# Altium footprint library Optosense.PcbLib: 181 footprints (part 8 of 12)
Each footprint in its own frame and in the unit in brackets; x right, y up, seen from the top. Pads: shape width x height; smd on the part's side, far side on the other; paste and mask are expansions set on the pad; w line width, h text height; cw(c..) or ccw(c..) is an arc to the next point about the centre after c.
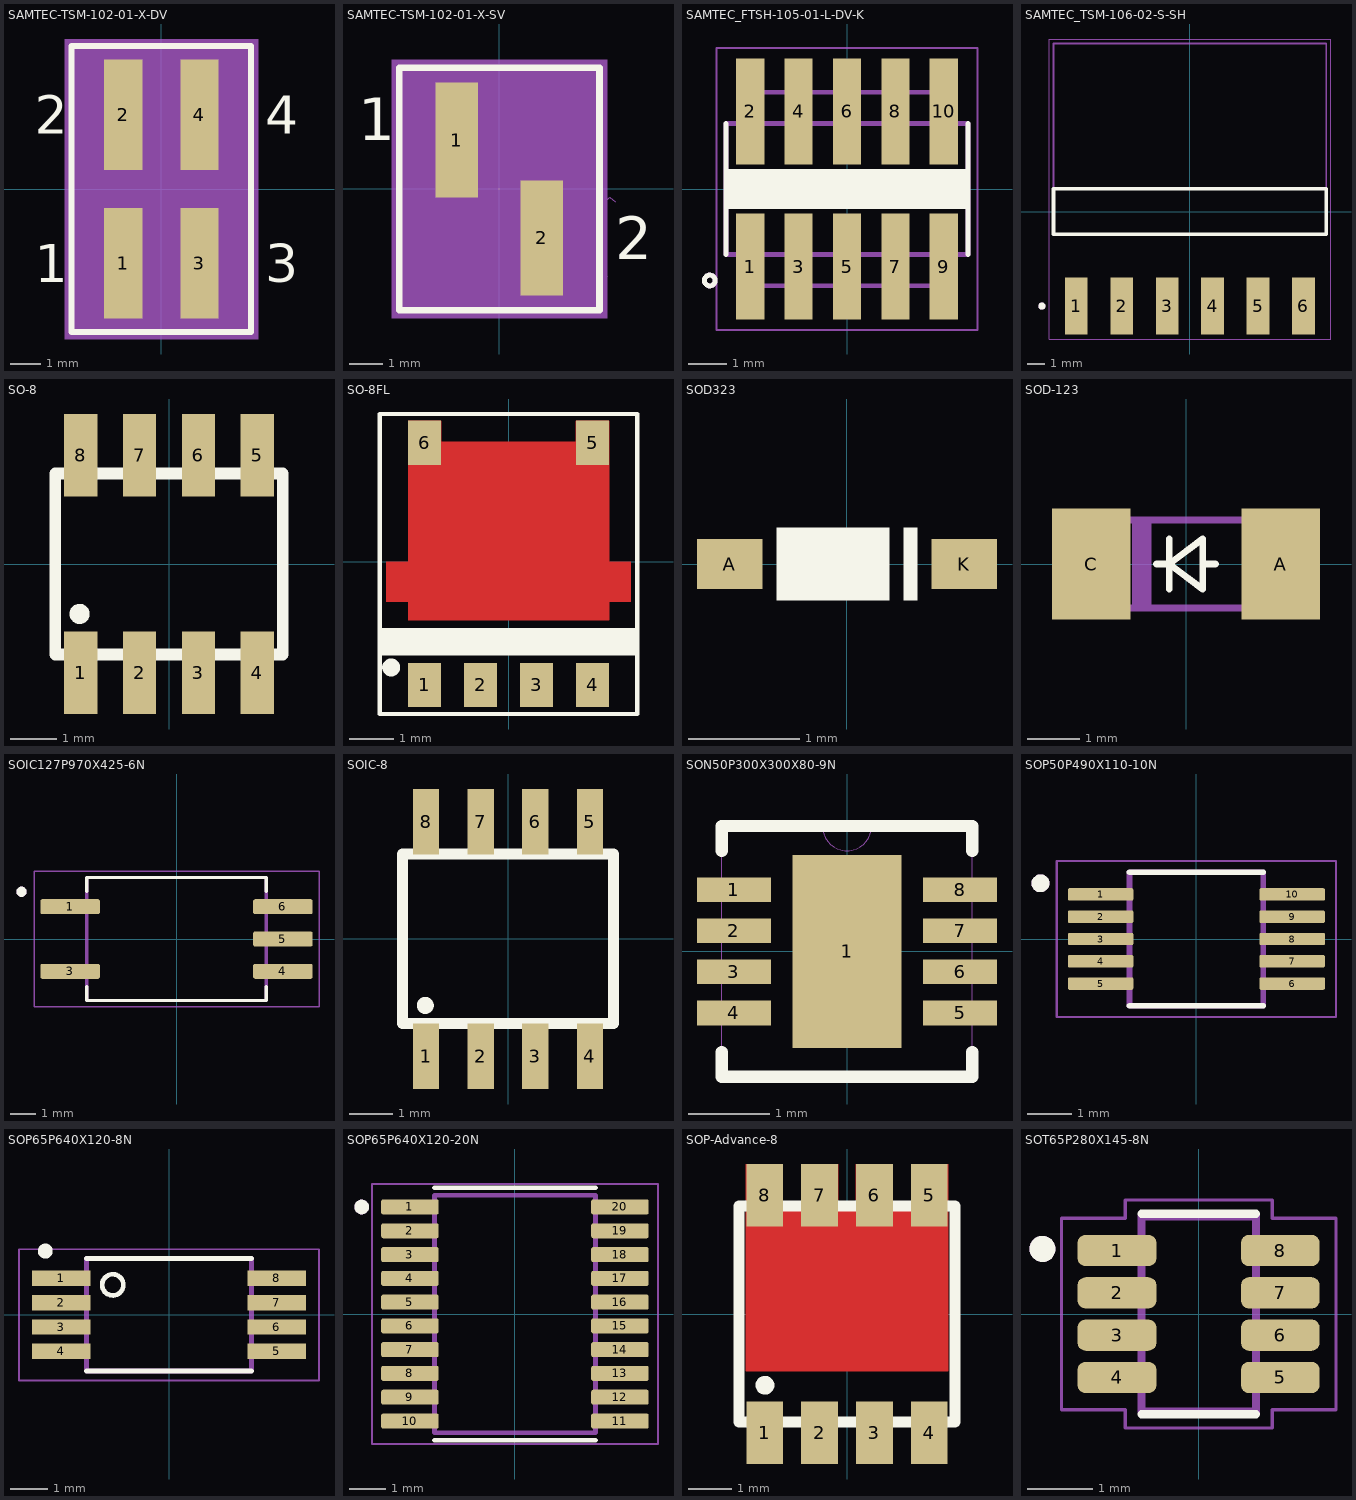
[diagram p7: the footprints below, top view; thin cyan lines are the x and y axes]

## SAMTEC-TSM-102-01-X-DV [mm]
pads (4):
  rect 1.27x3.68 smd mask+0: 1(-1.27,-2.476) 2(-1.27,2.476) 3(1.27,-2.476) 4(1.27,2.476)
Top Overlay:
  lines w0.2: -2.99,-4.768 2.99,-4.768 2.99,4.768 -2.99,4.768 -2.99,-4.768
  text "3" at 3.467,-3.112 h1.27
  text "2" at -4.226,1.842 h1.27
  text "1" at -4.226,-3.112 h1.27
  text "4" at 3.467,1.842 h1.27
Top Paste:
  region: 1.905,0.636 0.635,0.636 0.635,4.316 1.905,4.316
  region: 1.905,-4.316 0.635,-4.316 0.635,-0.636 1.905,-0.636
  region: -0.635,0.636 -1.905,0.636 -1.905,4.316 -0.635,4.316
  region: -0.635,-4.316 -1.905,-4.316 -1.905,-0.636 -0.635,-0.636
Top Solder:
  region: 1.956,0.585 0.584,0.585 0.584,4.367 1.956,4.367
  region: 1.956,-4.367 0.584,-4.367 0.584,-0.585 1.956,-0.585
  region: -0.584,0.585 -1.956,0.585 -1.956,4.367 -0.584,4.367
  region: -0.584,-4.367 -1.956,-4.367 -1.956,-0.585 -0.584,-0.585
Mechanical 13:
  lines w0: -0.635,4.699 0.635,4.699
  lines w0.1: -2.35,-0.762 -2.54,-0.762 -2.54,0.762 -2.35,0.762 ; -1.588,-2.54 -1.588,-3.848 -0.952,-3.848 -0.952,-2.54 ; -1.588,2.54 -1.588,3.848 -0.952,3.848 -0.952,2.54 ; -0.19,-0.762 0,-0.762 ; -0.19,0.762 0,0.762 ; 0.19,-0.762 0,-0.762 ; 0.19,0.762 0,0.762 ; 0.952,-2.54 0.952,-3.848 1.588,-3.848 1.588,-2.54 ; 0.952,2.54 0.952,3.848 1.588,3.848 1.588,2.54 ; 2.35,-0.762 2.54,-0.762 2.54,0.762 2.35,0.762 ; 0,-0.762 0,0.762 ; 0,-0.762 0,0.762 ; -2.99,-4.768 2.99,-4.768 2.99,4.768 -2.99,4.768 -2.99,-4.768 ; -2.35,-1.651 -2.35,-0.147 -1.905,-0.147 -1.905,0.147 -2.35,0.147 -2.35,1.651 -1.968,2.54 -0.572,2.54 -0.19,1.651 -0.19,0.147 -0.635,0.147 -0.635,-0.147 -0.19,-0.147 -0.19,-1.651 -0.572,-2.54 -1.968,-2.54 -2.35,-1.651 ; -1.588,-1.588 -0.952,-1.588 -0.952,-0.952 -1.588,-0.952 -1.588,-1.588 ; -1.588,0.952 -1.588,1.588 -0.952,1.588 -0.952,0.952 -1.588,0.952 ; 0.19,-1.651 0.19,-0.147 0.635,-0.147 0.635,0.147 0.19,0.147 0.19,1.651 0.572,2.54 1.968,2.54 2.35,1.651 2.35,0.147 1.905,0.147 1.905,-0.147 2.35,-0.147 2.35,-1.651 1.968,-2.54 0.572,-2.54 0.19,-1.651 ; 0.952,-1.588 1.588,-1.588 1.588,-0.952 0.952,-0.952 0.952,-1.588 ; 0.952,0.952 0.952,1.588 1.588,1.588 1.588,0.952 0.952,0.952
  text "3" at 3.467,-3.112 h1.27
  text "2" at -4.226,1.842 h1.27
  text "1" at -4.226,-3.112 h1.27
  text "4" at 3.467,1.842 h1.27
Mechanical 15:
  region: 3.225,-5.003 -3.225,-5.003 -3.225,5.003 3.225,5.003
3D body "TSM-102-01-F-DV.stp": height 9.61, standoff -0.04, extent -2.54,-3.848 2.54,3.848

## SAMTEC-TSM-102-01-X-SV [mm]
pads (2):
  rect 1.27x3.43 smd mask+0: 1(-1.27,1.46) 2(1.27,-1.46)
Top Overlay:
  lines w0.2: -2.99,-3.627 2.99,-3.627 2.99,3.626 -2.99,3.626 -2.99,-3.627
  text "2" at 3.467,-2.096 h1.27
  text "1" at -4.226,1.46 h1.27
Top Paste:
  region: 1.905,-3.175 0.635,-3.175 0.635,0.255 1.905,0.255
  region: -0.635,-0.255 -1.905,-0.255 -1.905,3.175 -0.635,3.175
Top Solder:
  region: 1.956,-3.226 0.584,-3.226 0.584,0.306 1.956,0.306
  region: -0.584,-0.306 -1.956,-0.306 -1.956,3.226 -0.584,3.226
Mechanical 13:
  lines w0: 3.143,-2.54 3.223,-2.604 ; 3.143,-0.381 3.302,-0.254 ; 3.223,-0.318 3.302,-0.254 ; 3.381,-0.318 3.461,-0.381 3.302,-0.254
  lines w0.1: -1.586,0.318 -0.951,0.318 ; -1.586,0.318 -1.586,1.27 -1.586,2.642 -0.951,2.642 -0.951,1.27 -0.951,0.318 ; -1.586,0.318 -1.586,-0.318 -0.951,-0.318 -0.951,0.318 ; 0,-1.016 0.106,-1.016 0.253,-1.27 2.54,-1.27 2.54,-1.016 2.54,1.016 2.54,1.27 0.253,1.27 0.106,1.016 0,1.016 ; 0,-1.016 0,1.016 ; 0,-1.016 -0.106,-1.016 -0.253,-1.27 -2.54,-1.27 -2.54,-1.016 -2.54,1.016 -2.54,1.27 -0.253,1.27 -0.106,1.016 0,1.016 ; 0,-1.016 0,1.016 ; 0.951,-0.318 1.586,-0.318 ; 0.951,-0.318 0.951,0.318 1.586,0.318 1.586,-0.318 ; 0.951,-0.318 0.951,-1.27 0.951,-2.642 1.586,-2.642 1.586,-1.27 1.586,-0.318 ; -2.99,-3.627 2.99,-3.627 2.99,3.626 -2.99,3.626 -2.99,-3.627
  text "2" at 3.467,-2.096 h1.27
  text "1" at -4.226,1.46 h1.27
Mechanical 15:
  region: 3.225,-3.862 -3.225,-3.862 -3.225,3.861 3.225,3.861
3D body "TSM-102-01-F-SV.stp": height 9.65, standoff 0, extent -2.54,-2.641 2.54,2.642

## SAMTEC_FTSH-105-01-L-DV-K [mm]
pads (10):
  rect 0.74x2.79 smd: 1(-2.54,-2.035) 2(-2.54,2.035) 3(-1.27,-2.035) 4(-1.27,2.035) 5(0,-2.035) 6(0,2.035) 7(1.27,-2.035) 8(1.27,2.035) 9(2.54,-2.035) 10(2.54,2.035)
Top Overlay:
  circle w0.127: c-3.6,-2.4 r0.141
  rectangle: -3.175,-0.525 3.175,0.525
  lines w0.127: -3.175,-1.715 -3.175,1.715 ; 3.175,-1.715 3.175,1.715
Mechanical 13:
  circle w0.127: c-3.6,-2.4 r0.141
  lines w0.127: -2.54,-1.715 -3.175,-1.715 -3.175,1.715 -2.54,1.715 ; -2.54,-1.715 2.54,-1.715 ; -2.54,-1.715 -2.54,-2.54 2.54,-2.54 2.54,-1.715 ; -2.54,1.715 2.54,1.715 ; -2.54,1.715 -2.54,2.54 2.54,2.54 2.54,1.715 ; 2.54,-1.715 3.175,-1.715 3.175,1.715 2.54,1.715
Mechanical 15:
  lines w0.05: -3.425,-3.7 3.425,-3.7 3.425,3.7 -3.425,3.7 -3.425,-3.7
3D body "FTSH-105-01-L-DV-K.stp": height 6.11, standoff -0.01, extent -3.175,-2.921 3.175,2.921

## SAMTEC_TSM-106-02-S-SH [mm]
pads (6):
  rect 1.27x3.18 smd: 1(-6.35,-5.28) 2(-3.81,-5.28) 3(-1.27,-5.28) 4(1.27,-5.28) 5(3.81,-5.28) 6(6.35,-5.28)
Top Overlay:
  circle w0.2: c-8.27,-5.28 r0.1
  lines w0.2: -7.62,-1.27 7.62,-1.27 7.62,1.27 -7.62,1.27 -7.62,-1.27
Mechanical 13:
  circle w0.2: c-8.27,-5.28 r0.1
  lines w0.1: -7.62,-1.27 -7.62,9.4 7.62,9.4 7.62,-1.27 ; -7.62,-1.27 7.62,-1.27 ; -7.62,-1.27 -7.62,1.27 7.62,1.27 7.62,-1.27
Mechanical 15:
  lines w0.05: -7.87,-7.12 7.87,-7.12 7.87,9.65 -7.87,9.65 -7.87,-7.12
3D body "TSM-106-02-S-SH-P.stp": height 4.32, standoff 0, extent -7.62,-6.096 7.62,9.398

## SO-8 [mm]
height 1.55
pads (8):
  rect 0.72x1.78 smd: 1(-1.905,-2.34) 2(-0.635,-2.34) 3(0.635,-2.34) 4(1.905,-2.34) 5(1.905,2.34) 6(0.635,2.34) 7(-0.635,2.34) 8(-1.905,2.34)
Top Overlay:
  circle w0.254: c-1.925,-1.075 r0.09
  lines w0.254: -2.45,-1.95 2.45,-1.95 2.45,1.95 -2.45,1.95 -2.45,-1.95
3D body "CircuitWorks-SO-8.step": height 1.45, standoff 0, extent -2.438,-2.889 2.464,2.889

## SO-8FL [mm]
pads (6):
  rect 0.75x1 smd: 1(-1.905,-2.795) 2(-0.635,-2.795) 3(0.635,-2.795) 4(1.905,-2.795) 5(1.905,2.7) 6(-1.905,2.7)
Top Layer:
  rectangle: -0.94,-0.178 0.94,1.676
  region: -2.28,-1.33 2.28,-1.33 2.28,-0.905 2.775,-0.905 2.775,0 2.28,0 2.28,3.2 1.53,3.2 1.53,2.725 -1.53,2.725 -1.53,3.2 -2.28,3.2 -2.28,0 -2.775,0 -2.775,-0.905 -2.28,-0.905
Top Overlay:
  circle w0.2: c-2.665,-2.398 r0.103
  rectangle: -2.946,-2.125 2.921,-1.499
  lines w0.1: -2.921,-3.454 2.921,-3.454 2.921,3.353 -2.921,3.353 -2.921,-3.454
3D body "User Library-DFN8-5X6 DUAL.step": height 1.1, standoff 0, extent -2.575,-3.1 2.575,3.05

## SOD323 [mm]
pads (2):
  rect 0.59x0.45 smd: A(-1.055,0) K(1.055,0)
Top Overlay:
  rectangle: -0.635,-0.33 0.381,0.33
  rectangle: 0.508,-0.33 0.635,0.33
3D body "User Library-SOD-323.STEP": height -0.4, standoff -1.5, extent -1.305,-0.69 1.295,0.66

## SOD-123 [mm]
pads (2):
  rect 1.5x2.1 smd: A(1.8,0) C(-1.8,0)
Top Overlay:
  lines w0.127: -0.561,0 -0.318,0 ; -0.318,-0.476 -0.318,0 ; -0.318,0.476 -0.318,0 ; 0.561,0 0.318,0 ; -0.318,0 0.318,-0.476 0.318,0 ; -0.318,0 0.318,0.476 0.318,0
Mechanical 13:
  region: -1.587,-0.9 -1.95,-0.9 -1.95,0.9 -1.587,0.9
  region: 1.95,-0.9 1.587,-0.9 1.587,0.9 1.95,0.9
  region: -0.663,-0.9 -1.025,-0.9 -1.025,0.9 -0.663,0.9
  lines w0.127: -1.873,-0.835 1.873,-0.835 ; -1.873,0.835 1.873,0.835
3D body "MMSZ4684.STEP": height 1.44, standoff -0.01, extent -1.825,-0.775 1.825,0.775

## SOIC127P970X425-6N [mm]
pads (5):
  rrect25% 2.34x0.59 smd: 1(-4.185,1.27) 3(-4.185,-1.27) 4(4.185,-1.27) 5(4.185,0) 6(4.185,1.27)
Top Overlay:
  circle w0.2: c-6.1,1.86 r0.1
  lines w0.127: -3.53,-1.88 -3.53,-2.42 3.53,-2.42 3.53,-1.88 ; -3.53,1.88 -3.53,2.42 3.53,2.42 3.53,1.88
Mechanical 13:
  circle w0.2: c-6.1,1.86 r0.1
  lines w0.127: -3.53,-2.42 -3.53,2.42 3.53,2.42 3.53,-2.42 -3.53,-2.42
Mechanical 15:
  lines w0.05: -5.605,-2.67 -5.605,2.67 5.605,2.67 5.605,-2.67 -5.605,-2.67
3D body "User Library-4 Lead 6 SOIC.STEP": height 2.3, standoff 0, extent -3.171,-1.85 3.172,1.85

## SOIC-8 [mm]
pads (8):
  rect 0.61x1.52 smd: 1(-1.905,-2.735) 2(-0.635,-2.735) 3(0.635,-2.735) 4(1.905,-2.735) 5(1.905,2.725) 6(0.635,2.725) 7(-0.635,2.725) 8(-1.905,2.725)
Top Overlay:
  circle w0.254: c-1.925,-1.55 r0.071
  lines w0.254: -2.45,-1.975 -2.45,1.975 2.45,1.975 2.45,-1.975 -2.45,-1.975
3D body "User Library-SOIC8_4_9x3_9_1_53_p1_27.step": height 1.55, standoff -0.11, extent -2.45,-3 2.45,3

## SON50P300X300X80-9N [mil]
pads (9):
  rect 36x12 smd: 1(-55,30) 2(-55,10) 3(-55,-10) 4(-55,-30) 5(55,-30) 6(55,-10) 7(55,10) 8(55,30)
  rect 53x94 smd: 1(0,0)
Top Overlay:
  lines w6: -61,-49 -61,-61 61,-61 61,-49 ; -61,49 -61,61 61,61 61,49
Mechanical 13:
  lines w0: -12,61 ccw(c0,61) 12,61 ; -12,61 12,61 ; -12,61 -61,61 -61,-61 61,-61 61,61 12,61
3D body "INA333AIDRGR--3DModel-STEP-56544.STEP": height 31.5, standoff 0, extent -59.06,-59.06 59.06,59.06

## SOP50P490X110-10N [mm]
pads (10):
  rrect25% 1.47x0.28 smd: 1(-2.15,1) 2(-2.15,0.5) 3(-2.15,0) 4(-2.15,-0.5) 5(-2.15,-1) 6(2.15,-1) 7(2.15,-0.5) 8(2.15,0) 9(2.15,0.5) 10(2.15,1)
Top Overlay:
  circle w0.2: c-3.5,1.25 r0.1
  lines w0.127: -1.5,-1.5 1.5,-1.5 ; -1.5,1.5 1.5,1.5
Mechanical 13:
  circle w0.2: c-3.5,1.25 r0.1
  lines w0.127: -1.5,-1.5 1.5,-1.5 1.5,1.5 -1.5,1.5 -1.5,-1.5
Mechanical 15:
  lines w0.05: -3.135,-1.75 3.135,-1.75 3.135,1.75 -3.135,1.75 -3.135,-1.75
3D body "msop-10.SLDPRT": height 1.15, standoff 0, extent -2.45,-1.5 2.45,1.5

## SOP65P640X120-8N [mm]
pads (8):
  rect 1.56x0.41 smd: 1(-2.88,0.975) 2(-2.88,0.325) 3(-2.88,-0.325) 4(-2.88,-0.975) 5(2.88,-0.975) 6(2.88,-0.325) 7(2.88,0.325) 8(2.88,0.975)
Top Overlay:
  circle w0.2: c-3.3,1.7 r0.1
  circle w0.127: c-1.5,0.8 r0.283
  lines w0.127: -2.2,-1.5 2.2,-1.5 ; -2.2,1.5 2.2,1.5
Mechanical 13:
  lines w0.127: -2.2,-1.5 2.2,-1.5 2.2,1.5 -2.2,1.5 -2.2,-1.5
Mechanical 15:
  lines w0.05: -4,-1.75 4,-1.75 4,1.75 -4,1.75 -4,-1.75
3D body "M24C64-DFDW6TP.STEP": height 0.53, standoff -0.67, extent -3.2,-1.5 3.2,1.5

## SOP65P640X120-20N [mm]
pads (20):
  rrect25% 1.57x0.41 smd: 1(-2.87,2.925) 2(-2.87,2.275) 3(-2.87,1.625) 4(-2.87,0.975) 5(-2.87,0.325) 6(-2.87,-0.325) 7(-2.87,-0.975) 8(-2.87,-1.625) 9(-2.87,-2.275) 10(-2.87,-2.925) 11(2.87,-2.925) 12(2.87,-2.275) 13(2.87,-1.625) 14(2.87,-0.975) 15(2.87,-0.325) 16(2.87,0.325) 17(2.87,0.975) 18(2.87,1.625) 19(2.87,2.275) 20(2.87,2.925)
Top Overlay:
  circle w0.2: c-4.19,2.925 r0.1
  lines w0.127: -2.2,-3.45 2.2,-3.45 ; -2.2,3.45 2.2,3.45
Mechanical 13:
  circle w0.2: c-4.19,2.925 r0.1
  lines w0.127: -2.2,-3.25 2.2,-3.25 2.2,3.25 -2.2,3.25 -2.2,-3.25
Mechanical 15:
  lines w0.05: -3.91,-3.55 3.91,-3.55 3.91,3.55 -3.91,3.55 -3.91,-3.55
3D body "TXS0108EPWR.STEP": height 1.2, standoff 0, extent -3.2,-3.25 3.2,3.25

## SOP-Advance-8 [mm]
pads (8):
  rect 0.85x1.45 smd: 1(-1.905,-2.75) 2(-0.635,-2.75) 3(0.635,-2.75) 4(1.905,-2.75)
  rect 0.85x1.45 smd paste+0 mask+0: 5(1.905,2.75) 6(0.635,2.75) 7(-0.635,2.75) 8(-1.905,2.75)
Top Layer:
  region: -2.35,3.475 -2.35,-1.325 2.35,-1.325 2.35,3.475 1.5,3.475 1.5,2.425 1.05,2.425 1.05,3.475 0.2,3.475 0.2,2.425 -0.2,2.425 -0.2,3.475 -1.05,3.475 -1.05,2.425 -1.5,2.425 -1.5,3.475
Top Overlay:
  circle w0.254: c-1.9,-1.65 r0.09
  lines w0.254: -2.5,-2.5 2.5,-2.5 2.5,2.5 -2.5,2.5 -2.5,-2.5
3D body "CircuitWorks-SO-8.step": height 1.45, standoff 0, extent -2.464,-3.01 2.439,2.768

## SOT65P280X145-8N [mm]
pads (8):
  rrect50% 1.21x0.48 smd: 1(-1.255,0.975) 2(-1.255,0.325) 3(-1.255,-0.325) 4(-1.255,-0.975) 5(1.255,-0.975) 6(1.255,-0.325) 7(1.255,0.325) 8(1.255,0.975)
Top Overlay:
  circle w0.2: c-2.4,1 r0.1
  lines w0.127: -0.88,-1.54 0.88,-1.54 ; -0.88,1.54 0.88,1.54
Mechanical 13:
  circle w0.2: c-2.4,1 r0.1
  lines w0.127: -0.88,-1.5 0.88,-1.5 0.88,1.5 -0.88,1.5 -0.88,-1.5
Mechanical 15:
  lines w0.05: -2.11,-1.47 -2.11,1.47 -1.13,1.47 -1.13,1.75 1.13,1.75 1.13,1.47 2.11,1.47 2.11,-1.47 1.13,-1.47 1.13,-1.75 -1.13,-1.75 -1.13,-1.47 -2.11,-1.47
